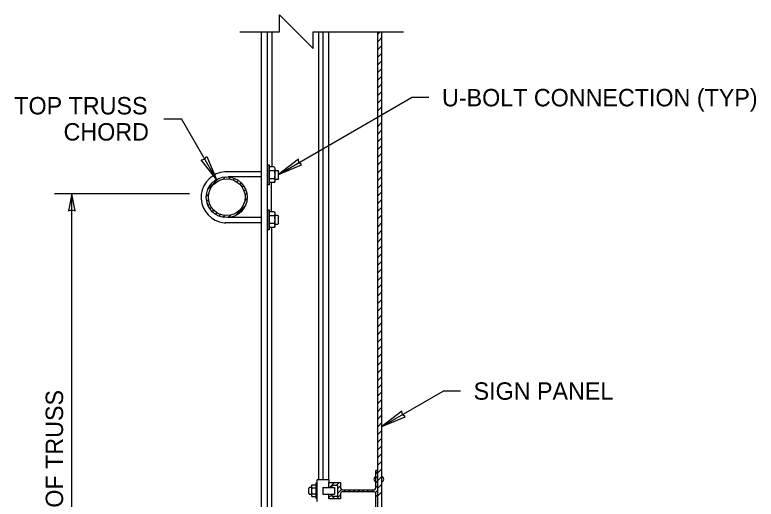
# Model space of a CAD drawing. Extents: x 99862 to 103151, y 100000 to 102076.
# Drawn here: x 101295 to 101977, y 101160 to 101606 of the extents above; entities that cross this region are included whole.
import ezdxf

# ---------------------------------------------------------------- set-up
doc = ezdxf.new("R2010")
doc.units = 0
for name, color, linetype in [('Level 1', 7, 'Continuous'), ('Level 10', 7, 'Continuous'), ('Level 13', 7, 'Continuous'), ('Level 14', 7, 'Continuous'), ('Level 15', 7, 'Continuous'), ('Level 2', 7, 'Continuous'), ('Level 20', 7, 'Continuous'), ('Level 27', 7, 'Continuous'), ('Level 4', 7, 'Continuous'), ('Level 5', 7, 'Continuous'), ('Level 8', 7, 'Continuous')]:
    doc.layers.add(name, color=color, linetype=linetype)

msp = doc.modelspace()

# ---------------------------------------------------------------- linework, layer by layer
at = {"layer": 'Level 1'}
for p, q in [((101628.87, 101587.84), (101631.04, 101590.01)), ((101628.87, 101580.77), (101632.62, 101584.52)), ((101628.87, 101573.7), (101632.62, 101577.45)), ((101628.87, 101566.63), (101632.62, 101570.38)), ((101628.87, 101559.56), (101632.62, 101563.31)), ((101628.87, 101552.49), (101632.62, 101556.24)), ((101628.87, 101545.42), (101632.62, 101549.17)), ((101628.87, 101538.35), (101632.62, 101542.1)), ((101628.87, 101531.28), (101632.62, 101535.03)), ((101628.87, 101524.2), (101632.62, 101527.95)), ((101628.87, 101517.13), (101632.62, 101520.88)), ((101628.87, 101502.99), (101632.62, 101506.74)), ((101628.87, 101495.92), (101632.62, 101499.67)), ((101628.87, 101488.85), (101632.62, 101492.6)), ((101628.87, 101481.78), (101632.62, 101485.53)), ((101628.87, 101474.71), (101632.62, 101478.46)), ((101628.87, 101467.64), (101632.62, 101471.39)), ((101628.87, 101460.34), (101632.62, 101464.09)), ((101628.87, 101453.27), (101632.62, 101457.02)), ((101628.87, 101446.19), (101632.62, 101449.94)), ((101628.87, 101439.12), (101632.62, 101442.87)), ((101628.87, 101432.05), (101632.62, 101435.8)), ((101628.87, 101424.98), (101632.62, 101428.73)), ((101628.87, 101417.91), (101632.62, 101421.66)), ((101628.87, 101410.84), (101632.62, 101414.59)), ((101628.87, 101403.77), (101632.62, 101407.52)), ((101628.87, 101396.7), (101632.62, 101400.45)), ((101628.87, 101389.63), (101632.62, 101393.38)), ((101628.87, 101382.55), (101632.62, 101386.3)), ((101628.87, 101375.48), (101632.62, 101379.23)), ((101628.87, 101368.41), (101632.62, 101372.16)), ((101628.87, 101361.34), (101632.62, 101365.09)), ((101628.87, 101354.27), (101632.62, 101358.02)), ((101628.87, 101347.2), (101632.62, 101350.95)), ((101628.87, 101340.13), (101632.62, 101343.88)), ((101628.87, 101333.06), (101632.62, 101336.81)), ((101628.87, 101325.99), (101632.62, 101329.74)), ((101628.87, 101318.92), (101632.62, 101322.67)), ((101628.87, 101311.84), (101632.62, 101315.59)), ((101628.87, 101304.77), (101632.62, 101308.52)), ((101628.87, 101297.7), (101632.62, 101301.45)), ((101628.87, 101290.63), (101632.62, 101294.38)), ((101628.87, 101283.56), (101632.62, 101287.31)), ((101628.87, 101276.49), (101632.62, 101280.24)), ((101628.87, 101269.42), (101632.62, 101273.17)), ((101628.87, 101262.35), (101632.62, 101266.1)), ((101628.87, 101255.28), (101632.62, 101259.03)), ((101628.87, 101248.2), (101632.62, 101251.95)), ((101628.87, 101241.13), (101632.62, 101244.88)), ((101628.87, 101234.06), (101632.62, 101237.81)), ((101628.87, 101226.99), (101632.62, 101230.74)), ((101628.87, 101219.92), (101632.62, 101223.67)), ((101628.87, 101212.85), (101632.62, 101216.6)), ((101628.87, 101205.78), (101632.62, 101209.53)), ((101628.87, 101198.71), (101632.62, 101202.46)), ((101628.87, 101191.64), (101632.62, 101195.39)), ((101628.87, 101184.56), (101632.62, 101188.31)), ((101628.87, 101177.49), (101632.62, 101181.24)), ((101628.87, 101170.42), (101632.62, 101174.17)), ((101628.87, 101163.35), (101632.62, 101167.1))]:
    msp.add_line(p, q, dxfattribs=at)
for points in [[(101628.87, 100753.22), (101628.87, 101110.01), (101628.87, 101590.01)], [(101632.62, 100753.22), (101632.62, 101107.92), (101632.62, 101590.01)]]:
    msp.add_open_spline(points, degree=2, dxfattribs=at)
at = {"layer": 'Level 10'}
for p, q in [((101529.05, 101465.69), (101529.05, 101462.1)), ((101533.61, 101465.69), (101529.05, 101465.69)), ((101533.61, 101465.69), (101534.16, 101464.73)), ((101533.61, 101462.1), (101529.05, 101462.1)), ((101534.16, 101464.73), (101534.16, 101463.98)), ((101534.16, 101463.98), (101534.16, 101463.81)), ((101534.16, 101463.81), (101534.16, 101458.67)), ((101534.16, 101462.51), (101534.16, 101454.23)), ((101534.16, 101458.67), (101534.16, 101458.37)), ((101533.61, 101454.94), (101529.05, 101454.94)), ((101534.16, 101452.31), (101533.61, 101451.35)), ((101534.16, 101458.37), (101534.16, 101453.19)), ((101534.16, 101453.19), (101534.16, 101453.11)), ((101534.16, 101453.11), (101534.16, 101452.31)), ((101533.61, 101451.35), (101529.05, 101451.35)), ((101529.05, 101424.44), (101529.05, 101420.85)), ((101533.61, 101424.44), (101529.05, 101424.44)), ((101533.61, 101424.44), (101534.16, 101423.48)), ((101533.61, 101420.85), (101529.05, 101420.85)), ((101534.16, 101423.48), (101534.16, 101422.73)), ((101534.16, 101422.73), (101534.16, 101422.56)), ((101534.16, 101422.56), (101534.16, 101417.42)), ((101534.16, 101421.26), (101534.16, 101412.98)), ((101533.61, 101413.69), (101529.05, 101413.69)), ((101534.16, 101411.06), (101533.61, 101410.1)), ((101534.16, 101417.42), (101534.16, 101417.12)), ((101534.16, 101417.12), (101534.16, 101411.94)), ((101534.16, 101411.94), (101534.16, 101411.86)), ((101534.16, 101411.86), (101534.16, 101411.06)), ((101533.61, 101410.1), (101529.05, 101410.1)), ((101568.36, 101173.49), (101567.94, 101172.77)), ((101567.94, 101172.77), (101567.94, 101172.21)), ((101568.36, 101173.49), (101571.78, 101173.49)), ((101571.78, 101173.49), (101571.78, 101170.8)), ((101565.81, 101171.11), (101565.38, 101170.37)), ((101565.38, 101165.65), (101565.38, 101170.37)), ((101565.38, 101165.65), (101565.82, 101164.9)), ((101567.94, 101171.11), (101565.81, 101171.11)), ((101567.94, 101172.21), (101567.94, 101172.08)), ((101567.94, 101172.08), (101567.94, 101168.23)), ((101567.94, 101171.11), (101567.94, 101164.9)), ((101567.94, 101168.23), (101567.94, 101168)), ((101567.94, 101168), (101567.94, 101164.12)), ((101568.36, 101170.8), (101571.78, 101170.8)), ((101565.81, 101164.9), (101567.94, 101164.9)), ((101567.94, 101164.12), (101567.94, 101164.06)), ((101567.94, 101164.06), (101567.94, 101163.46)), ((101567.94, 101163.46), (101568.36, 101162.74)), ((101568.36, 101165.43), (101571.78, 101165.43)), ((101568.36, 101162.74), (101571.78, 101162.74))]:
    msp.add_line(p, q, dxfattribs=at)
for points in [[(101529.05, 101467.71), (101529.05, 101449.32), (101527.67, 101449.32), (101527.67, 101467.71)], [(101529.05, 101426.46), (101529.05, 101408.07), (101527.67, 101408.07), (101527.67, 101426.46)], [(101571.78, 101175.01), (101571.78, 101161.22), (101572.82, 101161.22), (101572.82, 101175.01)]]:
    msp.add_lwpolyline(points, close=True, dxfattribs=at)
for points, degree in [([(101533.62, 101465.67), (101533.61, 101465.68), (101533.61, 101465.68), (101533.61, 101465.69)], 2), ([(101534.16, 101463.81), (101534.14, 101463.23), (101533.93, 101462.66), (101533.61, 101462.1)], 2), ([(101533.61, 101462.1), (101533.77, 101461.54), (101533.91, 101460.97), (101534.1, 101459.83), (101534.15, 101459.25), (101534.16, 101458.67)], 3), ([(101534.16, 101458.37), (101534.15, 101457.79), (101534.1, 101457.2), (101533.9, 101456.05), (101533.77, 101455.49), (101533.61, 101454.94)], 3), ([(101533.61, 101454.94), (101533.94, 101454.36), (101534.15, 101453.78), (101534.16, 101453.19)], 2), ([(101534.16, 101453.11), (101534.16, 101452.81), (101534.1, 101452.51), (101533.91, 101451.93), (101533.77, 101451.64), (101533.61, 101451.35)], 3), ([(101533.62, 101424.42), (101533.61, 101424.43), (101533.61, 101424.43), (101533.61, 101424.44)], 2), ([(101534.16, 101422.56), (101534.14, 101421.98), (101533.93, 101421.41), (101533.61, 101420.85)], 2), ([(101533.61, 101420.85), (101533.77, 101420.29), (101533.91, 101419.72), (101534.1, 101418.58), (101534.15, 101418), (101534.16, 101417.42)], 3), ([(101534.16, 101417.12), (101534.15, 101416.54), (101534.1, 101415.95), (101533.9, 101414.8), (101533.77, 101414.24), (101533.61, 101413.69)], 3), ([(101533.61, 101413.69), (101533.94, 101413.11), (101534.15, 101412.53), (101534.16, 101411.94)], 2), ([(101534.16, 101411.86), (101534.16, 101411.56), (101534.1, 101411.26), (101533.91, 101410.68), (101533.77, 101410.39), (101533.61, 101410.1)], 3), ([(101568.35, 101173.48), (101568.36, 101173.48), (101568.36, 101173.49), (101568.36, 101173.49)], 2), ([(101567.94, 101172.08), (101567.96, 101171.65), (101568.12, 101171.22), (101568.36, 101170.8)], 2), ([(101568.36, 101170.8), (101568.24, 101170.39), (101568.14, 101169.96), (101567.99, 101169.1), (101567.95, 101168.67), (101567.94, 101168.23)], 3), ([(101567.94, 101168), (101567.95, 101167.57), (101567.99, 101167.13), (101568.14, 101166.27), (101568.24, 101165.85), (101568.36, 101165.43)], 3), ([(101568.36, 101165.43), (101568.11, 101165), (101567.95, 101164.56), (101567.94, 101164.12)], 2), ([(101567.94, 101164.06), (101567.95, 101163.83), (101567.99, 101163.61), (101568.13, 101163.17), (101568.24, 101162.96), (101568.36, 101162.74)], 3)]:
    msp.add_open_spline(points, degree=degree, dxfattribs=at)
at = {"layer": 'Level 13'}
for centre, start, end in [((101628.15, 101178.71), 114.23756, 245.76244), ((101631.46, 101178.71), 0, 65.76244), ((101631.46, 101178.71), 294.23756, 0)]:
    msp.add_arc(centre, 2.81, start, end, dxfattribs=at)
at = {"layer": 'Level 14'}
for p, q in [((101472.88, 101445.39), (101482.52, 101455.02)), ((101486.89, 101454.45), (101489, 101456.56)), ((101492.02, 101454.62), (101493.63, 101456.24)), ((101495.99, 101453.65), (101497.41, 101455.06)), ((101499.27, 101451.98), (101500.62, 101453.33)), ((101502, 101449.76), (101503.3, 101451.06)), ((101504.2, 101447.01), (101505.55, 101448.35)), ((101505.85, 101443.71), (101507.28, 101445.14)), ((101471.32, 101438.87), (101473.44, 101441)), ((101506.8, 101439.71), (101508.42, 101441.32)), ((101471.66, 101434.26), (101473.27, 101435.87)), ((101472.82, 101430.48), (101474.24, 101431.9)), ((101506.56, 101434.52), (101508.72, 101436.68)), ((101474.57, 101427.27), (101475.91, 101428.62)), ((101476.83, 101424.59), (101478.13, 101425.89)), ((101497.86, 101420.87), (101507.04, 101430.05)), ((101479.52, 101422.33), (101480.88, 101423.68)), ((101482.76, 101420.62), (101484.18, 101422.04)), ((101486.56, 101419.47), (101488.18, 101421.09)), ((101491.2, 101419.15), (101493.37, 101421.33))]:
    msp.add_line(p, q, dxfattribs=at)
for radius in [18.75, 16.88]:
    msp.add_circle((101490.02, 101437.87), radius, dxfattribs=at)
at = {"layer": 'Level 15'}
for p, q in [((101537.58, 101458.78), (101659.89, 101529.4)), ((101675.89, 101529.4), (101659.89, 101529.4)), ((101432.38, 101509.98), (101448.38, 101509.98)), ((101480.64, 101454.1), (101448.38, 101509.98)), ((101455.76, 101441.13), (101331.76, 101441.13)), ((101347.52, 100897.9), (101347.76, 101441.16)), ((101632.62, 101227.29), (101688.91, 101259.79)), ((101704.91, 101259.79), (101688.91, 101259.79))]:
    msp.add_line(p, q, dxfattribs=at)
msp.add_lwpolyline([(101501.99, 101590.01), (101538.47, 101590.01), (101538.47, 101605.5), (101569.44, 101574.53), (101569.44, 101590.01), (101652.62, 101590.01)], dxfattribs=at)
for points in [[(101480.64, 101454.1), (101466.64, 101472.38), (101469.75, 101472.96), (101471.81, 101475.36)], [(101537.58, 101458.78), (101558.84, 101467.61), (101556.43, 101469.66), (101555.86, 101472.78)], [(101347.76, 101441.16), (101344.67, 101425.43), (101347.75, 101426.16), (101350.84, 101425.43)], [(101632.62, 101227.29), (101653.88, 101236.12), (101651.47, 101238.18), (101650.9, 101241.29)]]:
    msp.add_lwpolyline(points, close=True, dxfattribs=at)
at = {"layer": 'Level 2'}
for p, q in [((101521.99, 100753.22), (101521.99, 101590.01)), ((101527.62, 100753.22), (101527.62, 101590.01)), ((101578.24, 101590.01), (101578.24, 101178.43)), ((101583.87, 101178.43), (101583.87, 101590.01))]:
    msp.add_line(p, q, dxfattribs=at)
at = {"layer": 'Level 27'}
for p, q in [((101531.47, 101590.01), (101531.47, 101465.69)), ((101574.49, 101590.01), (101574.49, 101178.43)), ((101531.16, 101424.44), (101531.16, 101451.35)), ((101531.37, 100925.64), (101531.37, 101410.1))]:
    msp.add_line(p, q, dxfattribs=at)
at = {"layer": 'Level 4'}
for p, q in [((101626.99, 101170.55), (101626.99, 101186.87)), ((101628.87, 101186.87), (101626.99, 101186.87)), ((101626.99, 101183.83), (101628.87, 101185.71)), ((101626.99, 101179.59), (101628.87, 101181.47)), ((101583.87, 101171.12), (101583.87, 101175.62)), ((101583.87, 101175.62), (101594.74, 101175.62)), ((101584.58, 101171.11), (101589.08, 101175.62)), ((101586.49, 101172.99), (101586.49, 101171.12)), ((101592.12, 101172.99), (101586.49, 101172.99)), ((101590.69, 101172.99), (101593.32, 101175.62)), ((101592.12, 101163.24), (101592.12, 101172.99)), ((101592.12, 101170.17), (101594.74, 101172.8)), ((101594.74, 101175.62), (101594.74, 101170.55)), ((101626.99, 101175.35), (101628.87, 101177.22)), ((101626.99, 101171.1), (101628.87, 101172.98)), ((101586.49, 101171.12), (101583.87, 101171.12)), ((101592.12, 101165.93), (101595.48, 101169.29)), ((101594.74, 101165.68), (101594.74, 101160.62)), ((101596.24, 101169.05), (101625.49, 101169.05)), ((101625.49, 101167.18), (101596.24, 101167.18)), ((101597.61, 101167.18), (101599.48, 101169.05)), ((101601.85, 101167.18), (101603.73, 101169.05)), ((101606.1, 101167.18), (101607.97, 101169.05)), ((101610.34, 101167.18), (101612.21, 101169.05)), ((101614.58, 101167.18), (101616.46, 101169.05)), ((101618.82, 101167.18), (101620.7, 101169.05)), ((101623.07, 101167.18), (101624.94, 101169.05)), ((101626.68, 101166.55), (101628.87, 101168.74)), ((101626.99, 101149.37), (101626.99, 101165.68)), ((101583.87, 101165.12), (101586.49, 101165.12)), ((101583.87, 101160.62), (101583.87, 101165.12)), ((101583.87, 101161.92), (101586.49, 101164.55)), ((101594.74, 101160.62), (101583.87, 101160.62)), ((101586.49, 101165.12), (101586.49, 101163.24)), ((101586.49, 101163.24), (101592.12, 101163.24)), ((101586.8, 101160.62), (101589.43, 101163.24)), ((101591.05, 101160.62), (101594.74, 101164.31)), ((101626.99, 101162.62), (101628.87, 101164.49))]:
    msp.add_line(p, q, dxfattribs=at)
for centre, start, end in [((101596.24, 101170.55), 180, 270), ((101596.24, 101165.68), 90, 180), ((101625.49, 101170.55), 270, 0), ((101625.49, 101165.68), 360, 90)]:
    msp.add_arc(centre, 1.5, start, end, dxfattribs=at)
at = {"layer": 'Level 5'}
for p, q in [((101572.82, 101177.88), (101572.82, 101158.35)), ((101573.83, 101178.43), (101577.35, 101178.43)), ((101577.35, 101178.43), (101581.8, 101178.43)), ((101581.8, 101178.43), (101584.13, 101178.43)), ((101584.13, 101175.62), (101584.13, 101178.43)), ((101578.43, 101171.11), (101578.43, 101165.11)), ((101578.43, 101171.11), (101580.35, 101171.11)), ((101580.35, 101171.11), (101589.11, 101171.11)), ((101589.11, 101171.12), (101589.11, 101165.11)), ((101578.43, 101165.11), (101580.35, 101165.11)), ((101580.35, 101165.11), (101589.11, 101165.11))]:
    msp.add_line(p, q, dxfattribs=at)
msp.add_ellipse((101579.19, 101177.88), major_axis=(6.38, 0), ratio=0.158525, start_param=2.571061, end_param=3.141593, dxfattribs=at)
at = {"layer": 'Level 8'}
for p, q in [((101521.99, 101461.31), (101488.48, 101461.31)), ((101534.16, 101462.51), (101537.01, 101462.51)), ((101537.01, 101462.51), (101537.58, 101461.52)), ((101537.58, 101455.23), (101537.58, 101461.52)), ((101521.99, 101456.56), (101491.43, 101456.56)), ((101537.01, 101454.23), (101534.16, 101454.23)), ((101537.58, 101455.23), (101537, 101454.23)), ((101521.99, 101419.14), (101491, 101419.14)), ((101534.16, 101421.26), (101537.01, 101421.26)), ((101537.01, 101421.26), (101537.58, 101420.27)), ((101537.58, 101413.98), (101537.58, 101420.27)), ((101521.99, 101414.39), (101489.06, 101414.39)), ((101537.01, 101412.98), (101534.16, 101412.98)), ((101537.58, 101413.98), (101537, 101412.98))]:
    msp.add_line(p, q, dxfattribs=at)
for start, end in [(93.92688, 253.40217), (253.40217, 267.55527)]:
    msp.add_arc((101490.02, 101437.87), 23.5, start, end, dxfattribs=at)

# ---------------------------------------------------------------- texts
at = {"layer": 'Level 20'}
for s, rotation, p in [('U-BOLT CONNECTION (TYP)', 360, (101687.89, 101521.4)), ('DEPTH OF TRUSS', 90, (101339.64, 101074.16))]:
    msp.add_text(s, height=16, rotation=rotation, dxfattribs=at).set_placement(p)
for s, p in [('TOP TRUSS', (101294.82, 101513.98)), ('CHORD', (101340.09, 101489.98)), ('SIGN PANEL', (101716.91, 101251.79))]:
    msp.add_text(s, height=16, dxfattribs=at).set_placement(p)

doc.saveas('drawing.dxf')
